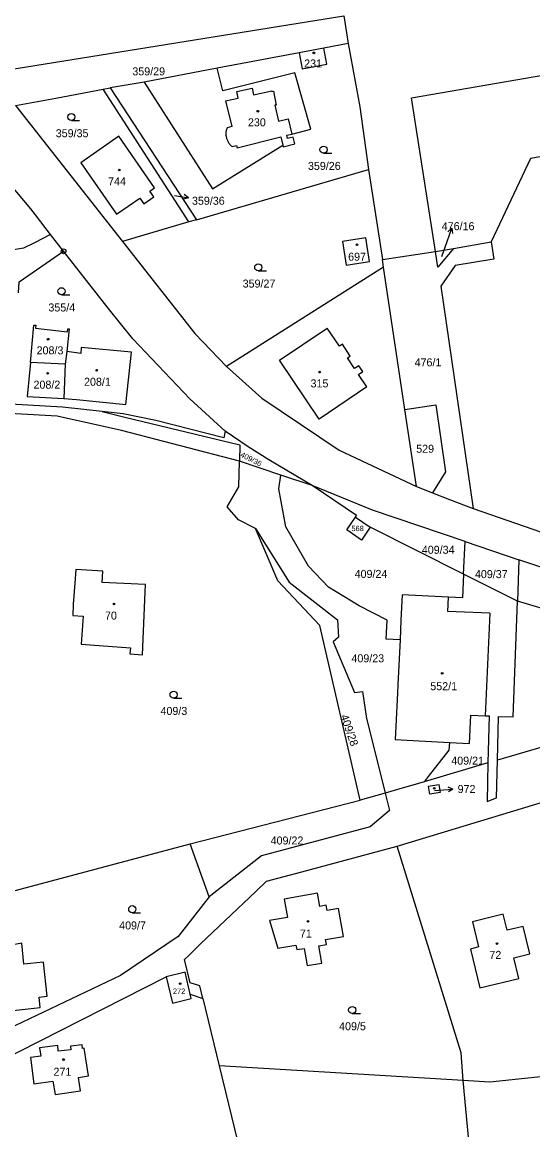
# Model space of a CAD drawing. Extents: x -725728 to -720881, y -1068679 to -1063504.
# Drawn here: x -724100.1 to -723991.6, y -1067188.2 to -1066953 of the extents above; entities that cross this region are included whole.
import ezdxf

# ---------------------------------------------------------------- set-up
doc = ezdxf.new("R2010")
doc.units = 0
for name, color, linetype in [('Hranice parcel', 7, 'Continuous'), ('Parcelní čísla', 7, 'Continuous'), ('Pop  PČ popisy', 7, 'Continuous'), ('Vnitřní kresba', 7, 'Continuous'), ('Značky bodu BP', 7, 'Continuous'), ('Značky budov', 7, 'Continuous'), ('Značky kultur', 7, 'Continuous')]:
    doc.layers.add(name, color=color, linetype=linetype)

# ---------------------------------------------------------------- blocks, each defined once
blk = doc.blocks.new('4.02_3')
at = {"layer": 'Značky budov'}
blk.add_circle((-0.001, 0), 0.0175, dxfattribs=at)
blk = doc.blocks.new('4.02_4')
at = {"layer": 'Značky budov'}
blk.add_circle((-0.001, 0), 0.0175, dxfattribs=at)
blk = doc.blocks.new('1029_81')
at = {"layer": 'Pop  PČ popisy'}
for p, q in [((0, 0), (0.299, 0.026)), ((0.299, 0.026), (0.195, 0.067)), ((0.299, 0.026), (0.204, -0.032))]:
    blk.add_line(p, q, dxfattribs=at)
blk = doc.blocks.new('1029_98')
at = {"layer": 'Pop  PČ popisy'}
for p, q in [((0, 0), (0.098, 0.284)), ((0.098, 0.284), (0.018, 0.205)), ((0.098, 0.284), (0.112, 0.173))]:
    blk.add_line(p, q, dxfattribs=at)
blk = doc.blocks.new('1029_106')
at = {"layer": 'Pop  PČ popisy'}
for p, q in [((0, 0), (0.296, -0.047)), ((0.296, -0.047), (0.205, 0.018)), ((0.296, -0.047), (0.19, -0.081))]:
    blk.add_line(p, q, dxfattribs=at)
blk = doc.blocks.new('3.04_2')
at = {"layer": 'Značky kultur'}
blk.add_line((0.001, 0), (0.176, 0), dxfattribs=at)
blk.add_circle((0.001, 0.075), 0.075, dxfattribs=at)
blk = doc.blocks.new('3.04_3')
at = {"layer": 'Značky kultur'}
blk.add_line((0.001, 0), (0.176, 0), dxfattribs=at)
blk.add_circle((0.001, 0.075), 0.075, dxfattribs=at)
blk = doc.blocks.new('1.05_2')
at = {"layer": 'Značky bodu BP'}
for radius in [0.05, 0.00303]:
    blk.add_circle((0, 0), radius, dxfattribs=at)

msp = doc.modelspace()

# ---------------------------------------------------------------- linework, layer by layer
at = {"layer": 'Hranice parcel'}
for p, q in [((-724114.08, -1066964.9), (-724031.79, -1066951.62)), ((-724031.79, -1066951.62), (-724030.84, -1066957.54)), ((-724036.02, -1066958.52), (-724041.26, -1066959.5)), ((-724030.84, -1066957.54), (-724036.02, -1066958.52)), ((-724041.26, -1066959.5), (-724058.67, -1066962.78)), ((-724058.67, -1066962.78), (-724074.22, -1066965.71)), ((-724074.22, -1066965.71), (-724081.39, -1066966.96)), ((-724082.93, -1066967.23), (-724081.39, -1066966.96)), ((-724064.73, -1066995.43), (-724082.93, -1066967.23)), ((-724081.39, -1066966.96), (-724063.11, -1066994.96)), ((-724101.56, -1066970.7), (-724078.79, -1066999.54)), ((-724063.11, -1066994.96), (-724026.56, -1066984.26)), ((-724026.56, -1066984.26), (-724023.56, -1067003.39)), ((-724064.73, -1066995.43), (-724078.79, -1066999.54)), ((-724063.11, -1066994.96), (-724064.73, -1066995.43)), ((-724094.09, -1066998.12), (-724097.52, -1066999.84)), ((-724091.31, -1067001.66), (-724094.09, -1066998.12)), ((-724012.29, -1067001.71), (-724008.48, -1067001.04)), ((-724008.48, -1067001.04), (-724000.49, -1066999.63)), ((-724081.84, -1067013.72), (-724091.31, -1067001.66)), ((-724023.56, -1067003.39), (-724012.29, -1067001.71)), ((-724023.37, -1067005), (-724023.56, -1067003.39)), ((-724023.37, -1067005), (-724056.67, -1067026.14)), ((-724018.8, -1067035.27), (-724023.37, -1067005)), ((-724090.15, -1067018.11), (-724090.64, -1067022.96)), ((-724090.64, -1067022.96), (-724090.95, -1067025.61)), ((-724098.36, -1067025.29), (-724099.09, -1067032.48)), ((-724090.95, -1067025.61), (-724098.36, -1067025.29)), ((-724090.95, -1067025.61), (-724091.3, -1067032.94)), ((-724099.09, -1067032.48), (-724091.3, -1067032.94)), ((-724016.36, -1067051.63), (-724018.8, -1067035.27)), ((-724052.1, -1067043.21), (-724057, -1067039.88)), ((-724045.19, -1067049.17), (-724053.94, -1067046.24)), ((-724038.49, -1067051.41), (-724045.19, -1067049.17)), ((-724016.36, -1067051.63), (-724012.96, -1067052.95)), ((-724004.3, -1067056.3), (-723918.53, -1067085.86)), ((-724029.28, -1067058.11), (-724026.15, -1067060.26)), ((-724006.33, -1067070.23), (-724026.15, -1067060.26)), ((-724006.33, -1067070.23), (-724005.98, -1067063.31)), ((-724005.98, -1067063.31), (-723994.57, -1067067.16)), ((-723994.57, -1067067.16), (-723994.9, -1067075.98)), ((-723929.19, -1067089.18), (-723994.57, -1067067.16)), ((-724088.92, -1067072.11), (-724089.25, -1067076.6)), ((-723994.9, -1067075.98), (-724006.33, -1067070.23)), ((-723939.41, -1067092.18), (-723994.9, -1067075.98)), ((-723939.41, -1067092.18), (-723999.15, -1067109.72)), ((-724001.15, -1067110.31), (-724014.69, -1067114.29)), ((-724014.69, -1067114.29), (-724015.91, -1067114.65)), ((-724022.99, -1067116.7), (-724028.29, -1067118.24)), ((-724021.08, -1067116.16), (-724022.99, -1067116.7)), ((-724015.91, -1067114.65), (-724021.08, -1067116.16)), ((-724020.45, -1067128.01), (-723982.05, -1067116.32)), ((-724064.4, -1067127.52), (-724028.29, -1067118.24)), ((-724104.52, -1067138.21), (-724064.4, -1067127.52)), ((-724060.41, -1067138.73), (-724064.4, -1067127.52)), ((-724106.26, -1067174.37), (-724069.53, -1067155.74)), ((-724064.43, -1067159.4), (-724061.72, -1067160.35)), ((-724061.72, -1067160.35), (-724058.26, -1067174.62)), ((-724006.45, -1067177.73), (-724058.26, -1067174.62)), ((-724058.26, -1067174.62), (-724043.61, -1067235.06)), ((-724001.32, -1067230.38), (-724006.45, -1067177.73))]:
    msp.add_line(p, q, dxfattribs=at)
for points in [[(-724041.26, -1066959.5), (-724040.61, -1066962.93), (-724035.38, -1066961.94), (-724036.02, -1066958.52)], [(-724030.84, -1066957.54), (-724028.4, -1066970.98), (-724026.56, -1066984.26)], [(-724074.22, -1066965.71), (-724059.68, -1066988.42), (-724044.73, -1066979.08), (-724044.64, -1066979.46), (-724042.18, -1066978.85), (-724042.53, -1066977.43), (-724043.71, -1066977.73), (-724043.89, -1066977.01), (-724042.8, -1066976.75), (-724038.78, -1066975.74), (-724042.17, -1066963.78), (-724057.46, -1066967.61), (-724058.67, -1066962.78)], [(-724012.29, -1067001.71), (-724017.4, -1066969.08), (-723977.15, -1066962.13)], [(-724101.56, -1066970.7), (-724092.99, -1066969.11), (-724082.93, -1066967.23)], [(-723921.75, -1066969.85), (-723965.76, -1066977.41), (-723992.14, -1066981.96), (-724000.49, -1066999.63)], [(-724094.09, -1066998.12), (-724094.8, -1066997.2), (-724097.3, -1066993.92), (-724098.27, -1066992.62), (-724104.56, -1066985.14), (-724107.82, -1066981.76), (-724111.79, -1066979.2), (-724116.06, -1066977.21), (-724120.58, -1066975.94), (-724130.87, -1066974.54)], [(-724072.97, -1066988.86), (-724071.97, -1066988.16), (-724079.56, -1066977.23), (-724087.64, -1066982.89), (-724080.07, -1066993.8), (-724075.14, -1066990.37)], [(-724075.14, -1066990.37), (-724074.28, -1066991.6), (-724072.11, -1066990.1), (-724072.97, -1066988.86)], [(-724032.07, -1066999.55), (-724031.28, -1067004.6), (-724026.29, -1067003.82), (-724027.08, -1066998.77), (-724032.07, -1066999.55)], [(-724097.52, -1066999.84), (-724099.8, -1067001.02), (-724100.23, -1067001.09), (-724124.47, -1067005.11)], [(-724078.79, -1066999.54), (-724063.4, -1067019.11), (-724056.67, -1067026.14)], [(-724008.48, -1067001.04), (-724011.78, -1067005), (-724012.29, -1067001.71)], [(-724000.49, -1066999.63), (-723999.88, -1067003.34), (-724008.15, -1067004.69), (-724011.15, -1067009.09), (-724004.3, -1067056.3)], [(-724100.92, -1067010.45), (-724100.75, -1067008.11), (-724091.31, -1067001.66)], [(-724057, -1067039.88), (-724064.52, -1067033.02), (-724076.59, -1067020.21), (-724081.84, -1067013.72)], [(-724098.36, -1067025.29), (-724097.61, -1067017.32), (-724097.23, -1067017.35), (-724097.3, -1067018), (-724090.5, -1067018.74), (-724090.45, -1067018.09), (-724090.15, -1067018.11)], [(-724091.3, -1067032.94), (-724088.6, -1067033.12), (-724078.06, -1067034.16), (-724076.91, -1067023.08), (-724087.56, -1067022.11)], [(-724087.56, -1067022.11), (-724087.62, -1067023.33), (-724090.64, -1067022.96)], [(-724056.67, -1067026.14), (-724049.23, -1067032.85), (-724032.79, -1067043.9), (-724016.36, -1067051.63)], [(-724083.13, -1067035.66), (-724091.57, -1067034.75), (-724102.59, -1067034.09), (-724102.51, -1067032.94)], [(-724018.8, -1067035.27), (-724012.24, -1067034.29), (-724010.2, -1067048.49), (-724012.96, -1067052.95)], [(-724053.94, -1067046.24), (-724079.03, -1067039.69), (-724092.71, -1067036.66), (-724116.77, -1067035.31)], [(-724057, -1067039.88), (-724057.29, -1067041.28), (-724071.73, -1067037.62), (-724078.69, -1067036.15), (-724083.13, -1067035.66)], [(-724083.13, -1067035.66), (-724078.31, -1067036.85), (-724053.87, -1067042.78), (-724053.94, -1067046.24)], [(-724038.49, -1067051.41), (-724047.73, -1067045.91), (-724052.1, -1067043.21)], [(-724050.54, -1067060.52), (-724054.16, -1067058.71), (-724056.56, -1067055.93), (-724054.05, -1067051.66), (-724053.94, -1067046.24)], [(-724019.83, -1067084.19), (-724022.81, -1067084.04), (-724022.59, -1067079.96), (-724028.5, -1067076.97), (-724035.04, -1067073.01), (-724039.26, -1067068.53), (-724044.08, -1067060.18), (-724045.55, -1067052.08), (-724045.19, -1067049.17)], [(-724029.28, -1067058.11), (-724029.1, -1067057.79), (-724038.49, -1067051.41)], [(-724005.98, -1067063.31), (-724025.71, -1067056.66), (-724038.49, -1067051.41)], [(-724012.96, -1067052.95), (-724009.36, -1067054.34), (-724004.3, -1067056.3)], [(-724026.15, -1067060.26), (-724028.01, -1067062.99), (-724031.15, -1067060.84), (-724029.28, -1067058.11)], [(-724028.29, -1067118.24), (-724036.85, -1067081.11), (-724045.81, -1067071.63), (-724050.54, -1067060.52)], [(-724050.54, -1067060.52), (-724043.39, -1067071.89), (-724033.15, -1067079.92), (-724032.91, -1067083.59), (-724034.05, -1067084.6), (-724029.53, -1067095.32), (-724027.81, -1067095.15), (-724026.94, -1067100.9), (-724025.9, -1067105.05), (-724022.99, -1067116.7)], [(-724089.25, -1067076.6), (-724089.38, -1067078.99), (-724087.19, -1067079.14), (-724087.6, -1067085.12), (-724077.13, -1067085.85), (-724077.22, -1067087.15), (-724074.58, -1067087.33), (-724074, -1067073.98), (-724073.93, -1067072.4), (-724083.14, -1067072), (-724082.97, -1067069.61), (-724088.7, -1067069.21), (-724088.92, -1067072.11)], [(-724006.33, -1067070.23), (-724006.59, -1067075.27), (-724009.56, -1067075.12), (-724019.36, -1067074.62), (-724019.63, -1067080.01), (-724019.83, -1067084.19)], [(-723999.15, -1067109.72), (-723998.94, -1067100.42), (-723995.82, -1067100.49), (-723994.9, -1067075.98)], [(-724019.83, -1067084.19), (-724020.3, -1067093.62), (-724020.39, -1067095.5), (-724020.87, -1067105.32), (-724009.36, -1067105.99)], [(-724009.36, -1067105.99), (-724005.11, -1067106.17), (-724004.78, -1067100.19), (-724001.78, -1067100.34), (-724000.93, -1067100.32), (-724001.15, -1067110.31)], [(-724009.36, -1067105.99), (-724009.45, -1067107.6), (-724013.83, -1067113.2), (-724014.69, -1067114.29)], [(-724001.15, -1067110.31), (-724001.33, -1067118.48), (-723999.32, -1067117.71), (-723999.15, -1067109.72)], [(-724022.99, -1067116.7), (-724022.06, -1067120.41), (-724026.19, -1067123.86), (-724049.3, -1067130.05), (-724060.41, -1067138.73)], [(-724011.33, -1067116.62), (-724013.49, -1067116.96), (-724013.78, -1067115.23), (-724011.6, -1067114.9), (-724011.33, -1067116.62)], [(-724061.72, -1067160.35), (-724062.37, -1067157.67), (-724064.4, -1067157.03), (-724065.62, -1067152.09), (-724064.71, -1067151.18), (-724062.26, -1067148.73), (-724050.47, -1067137.58), (-724048.22, -1067135.45), (-724040.71, -1067133.44), (-724020.45, -1067128.01)], [(-724006.45, -1067177.73), (-724006.87, -1067171.91), (-724020.45, -1067128.01)], [(-724040.22, -1067149.69), (-724039.58, -1067153.36), (-724036.43, -1067152.81), (-724037.07, -1067149.18), (-724035.47, -1067148.9), (-724035.66, -1067147.84), (-724031.84, -1067147.17), (-724032.88, -1067141.22), (-724035.3, -1067141.64), (-724035.5, -1067140.53), (-724036.9, -1067140.78), (-724037.39, -1067137.97), (-724044.45, -1067139.21), (-724043.77, -1067143.13), (-724047.54, -1067143.79), (-724045.81, -1067149.67), (-724041.94, -1067148.99), (-724041.77, -1067149.96), (-724040.22, -1067149.69)], [(-724060.41, -1067138.73), (-724066.95, -1067147.2), (-724079.25, -1067155.44), (-724106.07, -1067168.19), (-724134.41, -1067173.34)], [(-723994.6, -1067156.06), (-723995.67, -1067151.69), (-723992.27, -1067150.85), (-723993.7, -1067145.02), (-723997.1, -1067145.86), (-723997.94, -1067142.46), (-724004.45, -1067144.06), (-724003.13, -1067149.4), (-724004.88, -1067149.83), (-724002.85, -1067158.08), (-723994.6, -1067156.06)], [(-724095.6, -1067152.6), (-724099.74, -1067153.03), (-724100.21, -1067148.56), (-724102.08, -1067148.97), (-724103.06, -1067144.5), (-724109.2, -1067145.91), (-724106.42, -1067159.68), (-724103.06, -1067159.32), (-724102.68, -1067162.96), (-724096.27, -1067162.28), (-724096.51, -1067160.05), (-724094.83, -1067159.87), (-724095.6, -1067152.6)], [(-724064.43, -1067159.4), (-724065.51, -1067154.72), (-724069.53, -1067155.74)], [(-724069.53, -1067155.74), (-724068.19, -1067161.33), (-724064.2, -1067160.37), (-724064.43, -1067159.4)], [(-724092.57, -1067170.32), (-724096.41, -1067170.79), (-724096.16, -1067172.57), (-724098.34, -1067172.9), (-724097.63, -1067178.47), (-724093.58, -1067177.86), (-724093.14, -1067180.74), (-724087.72, -1067179.92), (-724088.15, -1067177.09), (-724086.05, -1067176.77), (-724086.93, -1067170.91), (-724087.27, -1067170.95), (-724087.36, -1067170.18), (-724089.88, -1067170.46), (-724089.79, -1067171.22), (-724092.44, -1067171.52), (-724092.57, -1067170.32)], [(-723967.05, -1067174.58), (-724000.78, -1067178.1), (-724006.45, -1067177.73)]]:
    msp.add_lwpolyline(points, dxfattribs=at)
at = {"layer": 'Pop  PČ popisy'}
for p, q in [((-724010.97, -1067002.76), (-724009.84, -1066999.57)), ((-724012.53, -1067116.19), (-724011.59, -1067116.11))]:
    msp.add_line(p, q, dxfattribs=at)
at = {"layer": 'Vnitřní kresba'}
for p, q in [((-724054.54, -1066967.74), (-724051.25, -1066967.03)), ((-724054.24, -1066969.15), (-724054.54, -1066967.74)), ((-724051.25, -1066967.03), (-724050.94, -1066968.44)), ((-724050.94, -1066968.44), (-724047.07, -1066967.6)), ((-724047.07, -1066967.6), (-724047.04, -1066967.75)), ((-724047.04, -1066967.75), (-724046.75, -1066967.68)), ((-724046.75, -1066967.68), (-724046.12, -1066970.59)), ((-724056.93, -1066969.73), (-724054.24, -1066969.15)), ((-724056.93, -1066969.73), (-724055.56, -1066975.18)), ((-724046.12, -1066970.59), (-724046.41, -1066970.65)), ((-724046.41, -1066970.65), (-724045.68, -1066974.04)), ((-724055.56, -1066975.18), (-724056.53, -1066975.42)), ((-724045.68, -1066974.04), (-724043.6, -1066973.53)), ((-724043.6, -1066973.53), (-724042.8, -1066976.75)), ((-724054.44, -1066979.67), (-724045.16, -1066977.38)), ((-724045.16, -1066977.38), (-724044.73, -1066979.08)), ((-724055.53, -1066979.43), (-724054.56, -1066979.19)), ((-724054.56, -1066979.19), (-724054.44, -1066979.67)), ((-724045.41, -1067024.77), (-724035.29, -1067017.99)), ((-724032.7, -1067021.83), (-724035.29, -1067017.99)), ((-724032.08, -1067021.41), (-724032.7, -1067021.83)), ((-724030.42, -1067023.89), (-724032.08, -1067021.41)), ((-724037.05, -1067037.29), (-724045.41, -1067024.77)), ((-724031.03, -1067024.3), (-724030.42, -1067023.89)), ((-724029.5, -1067026.57), (-724031.03, -1067024.3)), ((-724028.6, -1067025.96), (-724029.5, -1067026.57)), ((-724028.67, -1067027.81), (-724027.76, -1067027.2)), ((-724027.76, -1067027.2), (-724028.6, -1067025.96)), ((-724026.89, -1067030.45), (-724028.67, -1067027.81)), ((-724026.89, -1067030.45), (-724037.05, -1067037.29)), ((-724009.71, -1067078.12), (-724009.56, -1067075.12)), ((-724000.79, -1067078.5), (-724009.71, -1067078.12)), ((-724000.79, -1067078.5), (-724001.78, -1067100.34))]:
    msp.add_line(p, q, dxfattribs=at)
msp.add_lwpolyline([(-724055.53, -1066979.43), (-724055.66, -1066979.32), (-724055.77, -1066979.2), (-724055.89, -1066979.07), (-724055.99, -1066978.94), (-724056.1, -1066978.8), (-724056.19, -1066978.66), (-724056.28, -1066978.52), (-724056.36, -1066978.37), (-724056.44, -1066978.22), (-724056.5, -1066978.06), (-724056.56, -1066977.91), (-724056.61, -1066977.75), (-724056.66, -1066977.58), (-724056.7, -1066977.42), (-724056.73, -1066977.25), (-724056.75, -1066977.08), (-724056.76, -1066976.91), (-724056.77, -1066976.75), (-724056.77, -1066976.58), (-724056.75, -1066976.41), (-724056.74, -1066976.24), (-724056.71, -1066976.07), (-724056.68, -1066975.91), (-724056.64, -1066975.74), (-724056.59, -1066975.58), (-724056.53, -1066975.42)], dxfattribs=at)

# ---------------------------------------------------------------- block references
at = {"layer": 'Pop  PČ popisy', "xscale": 10, "yscale": 10}
for name, p in [('1029_106', (-724067.74, -1066989.8)), ('1029_98', (-724009.84, -1066999.57)), ('1029_81', (-724011.59, -1067116.11))]:
    msp.add_blockref(name, p, dxfattribs=at)
at = {"layer": 'Značky bodu BP', "xscale": 10, "yscale": 10}
msp.add_blockref('1.05_2', (-724091.31, -1067001.66), dxfattribs=at)
at = {"layer": 'Značky budov', "xscale": 10, "yscale": 10}
for name, p in [('4.02_3', (-724038.13, -1066959.51)), ('4.02_4', (-724050.03, -1066971.91)), ('4.02_4', (-724079.47, -1066984.4)), ('4.02_3', (-724028.95, -1067000.27)), ('4.02_3', (-724094.6, -1067020.32)), ('4.02_3', (-724094.69, -1067027.56)), ('4.02_4', (-724084.28, -1067026.91)), ('4.02_3', (-724036.89, -1067027.31)), ('4.02_3', (-724080.6, -1067076.55)), ('4.02_3', (-724010.87, -1067091.27)), ('4.02_3', (-724012.54, -1067115.7)), ('4.02_3', (-724039.39, -1067143.96)), ('4.02_4', (-723999.22, -1067148.67)), ('4.02_4', (-724066.54, -1067157.17)), ('4.02_3', (-724091.31, -1067173.31))]:
    msp.add_blockref(name, p, dxfattribs=at)
at = {"layer": 'Značky kultur', "xscale": 10, "yscale": 10}
for name, p in [('3.04_3', (-724089.68, -1066973.88)), ('3.04_2', (-724036.1, -1066980.82)), ('3.04_2', (-724049.97, -1067005.81)), ('3.04_3', (-724091.77, -1067010.88)), ('3.04_2', (-724067.96, -1067096.57)), ('3.04_2', (-724076.74, -1067142.12)), ('3.04_2', (-724030.01, -1067163.53))]:
    msp.add_blockref(name, p, dxfattribs=at)

# ---------------------------------------------------------------- texts
at = {"layer": 'Parcelní čísla'}
for s, height, p in [('231', 1.7, (-724040.2, -1066962.61)), ('359/29', 1.7, (-724076.71, -1066964.29)), ('359/35', 1.7, (-724092.98, -1066977.43)), ('230', 1.7, (-724052.15, -1066975.11)), ('359/26', 1.7, (-724039.4, -1066984.37)), ('744', 1.7, (-724081.86, -1066987.64)), ('359/36', 1.7, (-724064.04, -1066991.77)), ('476/16', 1.7, (-724010.97, -1066997.17)), ('697', 1.7, (-724030.86, -1067003.65)), ('359/27', 1.7, (-724053.27, -1067009.36)), ('355/4', 1.7, (-724094.54, -1067014.43)), ('208/3', 1.7, (-724097.05, -1067023.54)), ('476/1', 1.7, (-724016.74, -1067026.09)), ('208/2', 1.7, (-724097.71, -1067030.83)), ('208/1', 1.7, (-724086.97, -1067030.21)), ('315', 1.7, (-724038.85, -1067030.56)), ('529', 1.7, (-724016.4, -1067044.44)), ('568', 1.14, (-724030.16, -1067061.08)), ('409/34', 1.7, (-724015.21, -1067065.89)), ('409/24', 1.7, (-724029.48, -1067071.02)), ('409/37', 1.7, (-724003.92, -1067071.06)), ('70', 1.7, (-724082.52, -1067079.87)), ('409/23', 1.7, (-724030.16, -1067088.94)), ('552/1', 1.7, (-724013.4, -1067094.86)), ('409/3', 1.7, (-724070.73, -1067100.12)), ('409/21', 1.7, (-724008.95, -1067110.67)), ('972', 1.7, (-724007.6, -1067116.7)), ('409/22', 1.7, (-724047.33, -1067127.63)), ('409/7', 1.7, (-724079.51, -1067145.67)), ('71', 1.7, (-724041.11, -1067147.41)), ('72', 1.7, (-724000.85, -1067151.92)), ('272', 1.14, (-724068.09, -1067159.36)), ('409/5', 1.7, (-724032.78, -1067167.08)), ('271', 1.7, (-724093.46, -1067176.74))]:
    msp.add_text(s, height=height, dxfattribs=at).set_placement(p)
for s, height, rotation, p in [('409/36', 1.14, 333, (-724053.87, -1067045.21)), ('409/28', 1.7, 289, (-724032.52, -1067100.34))]:
    msp.add_text(s, height=height, rotation=rotation, dxfattribs=at).set_placement(p)

doc.saveas('drawing.dxf')
